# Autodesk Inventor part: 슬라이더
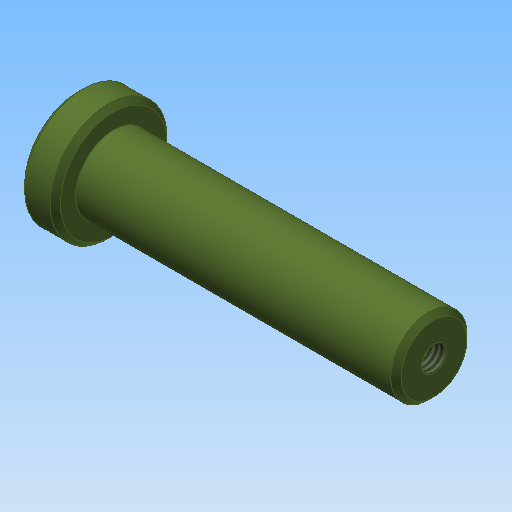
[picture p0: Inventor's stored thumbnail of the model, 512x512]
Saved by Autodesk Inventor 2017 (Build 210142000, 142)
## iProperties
Created: 2011-04
Part Number: 슬라이더
Document SubType Name: Modeling
Density: 1 g/cm^3
Material: 일반
Appearance: 올리브 녹색
Author: pww
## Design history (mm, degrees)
sketch "스케치1"
  geometry: L1 (-7, 0)-(63, 0); L2 (63, 0)-(63, 7.5); L3 (63, 7.5)-(0, 7.5); L4 (-7, 0)-(-7, 11.5); L5 (-7, 11.5)-(0, 11.5); L6 (0, 11.5)-(0, 7.5); 1 further point
  constraints: 12 end point, 3 perpendicular, 2 horizontal, 2 point on line, 1 parallel
  dimensions: "d1" = 70 distance of L1.start L1.end; "d19" = 15 diameter of L3 L1; "d20" = 7 distance of L4.end L5.end; "d21" = 23 diameter of L5 L1
revolve "회전1" stored, may be unused: angle "d4" = 90 deg
chamfer "모따기1" distance "d16" = 1; stored, may be unused: second distance "d17" = 2, angle "d18" = 45 deg
hole "구멍2" diameter "d24" = 4.917; stored, may be unused: countersink angle "d28" = 90 deg, drill point angle "d30" = 118 deg; dims "d22" = 10, "d23" = 10, "d25" = 10, "d26" = 4, "d27" = 2, "d29" = 13
node "솔리드1"
